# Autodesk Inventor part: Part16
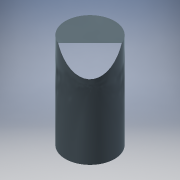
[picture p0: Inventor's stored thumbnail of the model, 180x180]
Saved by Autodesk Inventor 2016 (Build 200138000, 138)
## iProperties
Created: 2020-04
Part Number: Part16
Material: Generic
Document SubType Name: Modeling
Designer: merlin
Density: 1 g/cm^3
Appearance: Lead
Author: merlin
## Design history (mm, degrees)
sketch "Sketch1"
  geometry: C1 r 6.545 at (44.45, -457.2); 1 further point
  constraints: 1 centre point
  dimensions: "d0" = 25.4 dimension on point (0, 0) C1.centre C1
extrude "Extrusion1" new body sketch "Sketch1" distance "d0" = 25.4; taper "d1" = 0 deg
body "Solid1"
